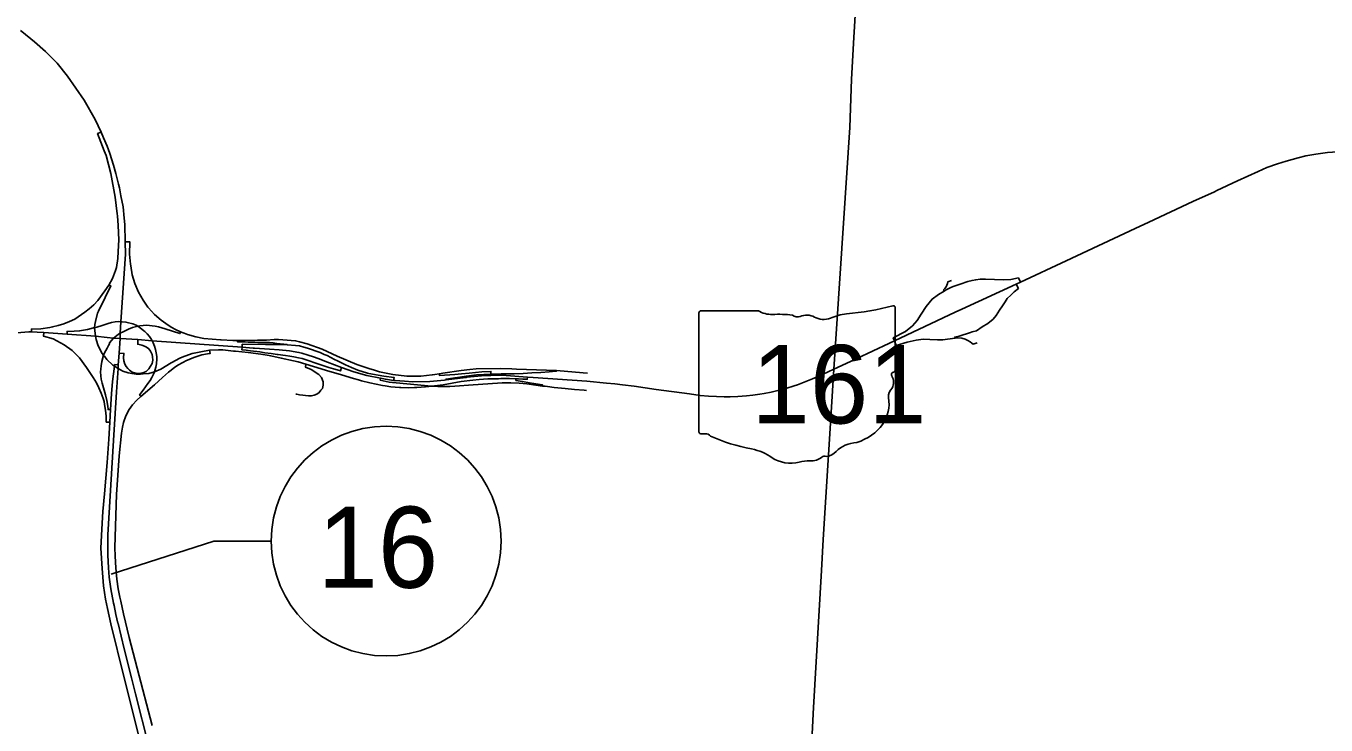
# Model space of a CAD drawing. Extents: x -1146 to -445, y -1283 to -822.
# Drawn here: x -822.8 to -765.1, y -965.9 to -934.9 of the extents above; entities that cross this region are included whole.
import ezdxf

# ---------------------------------------------------------------- set-up
doc = ezdxf.new("R2010")
doc.units = 0
for name, color, linetype in [('Default', 7, 'Continuous'), ('GM_X_Interchange_Ramps', 7, 'Continuous'), ('GM_X_Interstate_Route', 7, 'Continuous'), ('GM_X_State_Route', 7, 'Continuous'), ('GM_X_State_Shield', 7, 'Continuous'), ('GM_X_Township', 7, 'Continuous')]:
    doc.layers.add(name, color=color, linetype=linetype)

msp = doc.modelspace()

# ---------------------------------------------------------------- linework, layer by layer
at = {"layer": 'Default'}
msp.add_lwpolyline([(-811.901, -957.726), (-814.448, -957.726), (-818.997, -959.198)], dxfattribs=at)
msp.add_circle((-806.807, -957.726), 5.094, dxfattribs=at)
at = {"layer": 'GM_X_Interchange_Ramps'}
for points in [[(-819.448, -939.58), (-819.6, -939.647), (-819.307, -940.406), (-819.226, -940.617), (-819.015, -941.422), (-818.829, -942.461), (-818.73, -943.211), (-818.718, -943.301), (-818.686, -943.722), (-818.658, -944.358), (-818.683, -944.883), (-818.699, -945.182), (-818.768, -945.593), (-818.804, -945.721), (-818.948, -946.078), (-819.098, -946.367), (-819.275, -946.626), (-819.59, -947.048), (-819.772, -947.241), (-819.971, -947.421), (-820.168, -947.574), (-820.613, -947.874), (-820.85, -947.984), (-821.093, -948.082), (-821.344, -948.166), (-821.598, -948.227), (-821.723, -948.25), (-822.119, -948.304), (-822.534, -948.317), (-822.534, -948.445)], [(-797.886, -950.276), (-798.072, -950.259), (-799.257, -950.151), (-801.023, -950.096), (-801.236, -950.09), (-801.756, -950.069), (-802.815, -950.09), (-803.099, -950.118), (-803.474, -950.154), (-804.287, -950.272), (-804.454, -950.301), (-804.646, -950.334), (-804.765, -950.355), (-805.271, -950.409), (-805.889, -950.409), (-806.517, -950.332), (-807.104, -950.21), (-807.374, -950.132), (-807.534, -950.086), (-808.112, -949.893), (-808.976, -949.516), (-809.641, -949.212), (-810.31, -948.968), (-810.644, -948.885), (-810.824, -948.84), (-811.393, -948.791), (-811.583, -948.787), (-811.771, -948.788), (-812.109, -948.806), (-812.509, -948.815), (-813.053, -948.83), (-813.297, -948.829), (-813.407, -948.828), (-813.601, -948.826), (-814.123, -948.8), (-814.157, -948.798), (-814.523, -948.774), (-814.888, -948.736), (-815.252, -948.667), (-815.618, -948.558), (-815.77, -948.504), (-815.801, -948.493), (-815.926, -948.437), (-816.148, -948.337), (-816.316, -948.245), (-816.478, -948.147), (-816.789, -947.924), (-817.077, -947.669), (-817.347, -947.371), (-817.368, -947.343), (-817.586, -947.04), (-817.789, -946.68), (-817.95, -946.301), (-818.065, -945.91), (-818.131, -945.514), (-818.138, -945.446), (-818.186, -944.992), (-818.17, -944.456), (-818.379, -944.45)], [(-819.098, -946.367), (-819.016, -946.396), (-819.259, -946.914), (-819.56, -947.522), (-819.605, -947.612), (-819.7, -947.976), (-819.718, -948.11), (-819.738, -948.257), (-819.698, -948.64), (-819.67, -948.775), (-819.582, -949.062), (-819.477, -949.261), (-819.412, -949.383), (-819.341, -949.475), (-819.302, -949.525), (-819.188, -949.673), (-818.919, -949.92), (-818.847, -949.964), (-818.692, -950.074), (-818.488, -950.179), (-818.241, -950.265), (-818.078, -950.286), (-817.891, -950.315), (-817.705, -950.323), (-817.588, -950.312), (-817.331, -950.288), (-817.078, -950.215), (-816.805, -950.104), (-816.34, -949.824), (-816.307, -949.804), (-815.961, -949.616), (-815.781, -949.533), (-815.69, -949.5), (-815.406, -949.397), (-815.326, -949.381), (-815.022, -949.323), (-814.638, -949.25), (-814.247, -949.233), (-814.056, -949.242), (-813.578, -949.294), (-813.489, -949.304), (-812.92, -949.361), (-812.363, -949.436), (-811.999, -949.495), (-811.925, -949.51), (-811.461, -949.604), (-810.921, -949.726), (-810.707, -949.779), (-810.375, -949.874), (-809.684, -950.078), (-809.447, -950.15), (-808.794, -950.35), (-808.259, -950.512), (-808.038, -950.575), (-807.894, -950.615), (-807.528, -950.711), (-806.968, -950.826), (-806.846, -950.843), (-806.594, -950.877), (-806.217, -950.909), (-806.158, -950.912), (-805.835, -950.923), (-805.551, -950.917), (-805.453, -950.914), (-805.063, -950.887), (-804.77, -950.85), (-804.67, -950.837), (-804.278, -950.787), (-803.878, -950.716), (-803.475, -950.649), (-802.965, -950.587), (-802.689, -950.553), (-802.495, -950.54), (-802.302, -950.53), (-802.109, -950.523), (-801.832, -950.52), (-801.719, -950.519), (-801.526, -950.518), (-801.333, -950.519), (-801.051, -950.529), (-800.939, -950.527), (-800.745, -950.534), (-800.55, -950.542), (-800.542, -950.449)], [(-781.668, -946.432), (-781.764, -946.47), (-782.003, -946.598), (-782.063, -946.633), (-782.317, -946.782), (-782.596, -946.988), (-782.864, -947.319), (-783.082, -947.657), (-783.266, -947.941), (-783.472, -948.181), (-783.775, -948.428), (-784.322, -948.714), (-784.266, -948.841)], [(-781.743, -946.157), (-781.895, -946.218), (-781.913, -946.296), (-781.942, -946.378), (-781.98, -946.449), (-782.035, -946.524), (-782.09, -946.578), (-782.063, -946.633)], [(-778.681, -946.231), (-778.774, -946.051), (-779.104, -946.113), (-779.428, -946.132), (-780.238, -946.1), (-780.473, -946.106), (-780.661, -946.128), (-780.823, -946.161), (-781.015, -946.21), (-781.353, -946.324), (-781.539, -946.379), (-781.668, -946.432)], [(-780.822, -948.444), (-780.631, -948.394), (-780.377, -948.223), (-780.134, -948.076), (-779.897, -947.886), (-779.757, -947.713), (-779.607, -947.483), (-779.475, -947.292), (-779.361, -947.11), (-779.266, -946.967), (-779.113, -946.816), (-778.958, -946.665), (-778.774, -946.519), (-778.876, -946.323)], [(-817.69, -951.31), (-817.741, -951.246), (-817.679, -951.163), (-817.576, -951.023), (-817.473, -950.883), (-817.372, -950.74), (-817.277, -950.603), (-817.19, -950.464), (-817.118, -950.318), (-817.078, -950.215), (-817.026, -950.014), (-816.991, -949.857), (-816.987, -949.805), (-816.979, -949.695), (-816.982, -949.535), (-817.002, -949.376), (-817.036, -949.221), (-817.083, -949.071), (-817.143, -948.923), (-817.188, -948.838), (-817.216, -948.786), (-817.301, -948.655), (-817.402, -948.532), (-817.512, -948.422), (-817.548, -948.392), (-817.634, -948.32), (-817.824, -948.195), (-817.899, -948.153), (-818.043, -948.09), (-818.295, -948.024), (-818.349, -948.01), (-818.507, -947.992), (-818.567, -947.992), (-818.668, -947.99), (-818.825, -948.002), (-818.984, -948.027), (-819.138, -948.065), (-819.439, -948.169), (-819.738, -948.257), (-819.789, -948.271), (-820.045, -948.338), (-820.401, -948.398), (-820.644, -948.415), (-820.952, -948.425), (-820.958, -948.549)], [(-815.926, -948.437), (-815.95, -948.517), (-816.279, -948.418), (-816.601, -948.315), (-816.902, -948.224), (-817.055, -948.187), (-817.43, -948.142), (-817.725, -948.172), (-817.824, -948.195), (-818.052, -948.256), (-818.232, -948.328), (-818.433, -948.424), (-818.594, -948.497), (-818.638, -948.517), (-818.753, -948.602), (-818.901, -948.721), (-819.067, -948.936), (-819.081, -948.967), (-819.121, -949.05), (-819.175, -949.173), (-819.292, -949.376), (-819.325, -949.448), (-819.341, -949.475), (-819.414, -949.755), (-819.445, -949.943), (-819.461, -950.093), (-819.469, -950.221), (-819.458, -950.394), (-819.45, -950.541), (-819.398, -950.723), (-819.251, -951.231), (-819.187, -951.491), (-819.145, -951.739), (-819.14, -951.887), (-819.024, -951.888)], [(-821.988, -948.471), (-821.995, -948.64), (-821.572, -948.759), (-821.088, -949.019), (-820.732, -949.263), (-820.407, -949.602), (-820.092, -950.029), (-819.794, -950.463), (-819.656, -950.707), (-819.541, -950.926), (-819.442, -951.166), (-819.36, -951.4), (-819.316, -951.535), (-819.296, -951.667), (-819.252, -951.912), (-819.233, -952.056), (-819.228, -952.183), (-819.219, -952.444), (-819.064, -952.443)], [(-817.811, -948.787), (-817.824, -948.994), (-817.643, -949.028), (-817.527, -949.07), (-817.429, -949.123), (-817.334, -949.2), (-817.254, -949.303), (-817.186, -949.446), (-817.162, -949.557), (-817.159, -949.695), (-817.188, -949.84), (-817.252, -949.967), (-817.331, -950.089), (-817.455, -950.195), (-817.596, -950.256), (-817.683, -950.279), (-817.818, -950.285), (-817.958, -950.261), (-818.067, -950.224), (-818.189, -950.147), (-818.268, -950.073), (-818.339, -949.986), (-818.4, -949.869), (-818.443, -949.732), (-818.451, -949.599), (-818.435, -949.396), (-818.65, -949.39)], [(-784.266, -948.841), (-784.186, -949.044), (-783.706, -948.899), (-783.3, -948.809), (-782.996, -948.76), (-782.699, -948.788), (-782.353, -948.792), (-782.128, -948.795), (-781.91, -948.767), (-781.573, -948.726), (-781.436, -948.706), (-781.286, -948.721), (-781.134, -948.771), (-781.009, -948.823), (-780.907, -948.88), (-780.833, -948.941), (-780.781, -948.993), (-780.596, -948.923)], [(-781.573, -948.726), (-781.591, -948.672), (-781.405, -948.632), (-780.901, -948.47), (-780.822, -948.444)], [(-817.188, -965.901), (-817.841, -963.357), (-818.196, -961.995), (-818.449, -960.944), (-818.573, -960.385), (-818.609, -960.208), (-818.686, -959.835), (-818.746, -959.407), (-818.799, -958.911), (-818.824, -958.395), (-818.844, -958.003), (-818.759, -955.652), (-818.643, -953.947), (-818.547, -952.935), (-818.504, -952.673), (-818.452, -952.458), (-818.357, -952.167), (-818.206, -951.89), (-818.048, -951.678), (-817.863, -951.469), (-817.69, -951.31), (-817.086, -950.788), (-816.729, -950.469), (-816.462, -950.231), (-816.345, -950.14), (-816.173, -950.007), (-816.016, -949.902), (-815.852, -949.811), (-815.798, -949.783), (-815.682, -949.725), (-815.51, -949.647), (-815.334, -949.576), (-814.974, -949.468), (-814.731, -949.423), (-814.606, -949.399), (-814.638, -949.25)], [(-811.202, -949.025), (-811.2, -948.997), (-811.65, -948.952), (-811.817, -948.936), (-811.98, -948.922), (-812.105, -948.912), (-812.492, -948.909), (-812.634, -948.907), (-812.777, -948.904), (-812.921, -948.899), (-813.405, -948.881), (-813.407, -948.828)], [(-813.197, -949.124), (-813.205, -949.237), (-813.009, -949.256), (-812.826, -949.278), (-812.412, -949.334), (-812.192, -949.367), (-811.907, -949.407), (-811.638, -949.441), (-811.59, -949.447), (-811.395, -949.475), (-811.269, -949.494), (-811.085, -949.518), (-810.898, -949.553), (-810.695, -949.598)], [(-810.656, -949.063), (-810.831, -949.05), (-811.202, -949.025), (-811.494, -949.006), (-811.795, -948.998), (-812.16, -949.004), (-813.188, -948.99), (-813.197, -949.124)], [(-806.475, -950.596), (-806.456, -950.466), (-806.915, -950.408), (-807.575, -950.284), (-807.631, -950.274), (-808.061, -950.135), (-808.338, -950.027), (-808.607, -949.906), (-808.962, -949.733), (-809.091, -949.673), (-809.428, -949.494), (-809.549, -949.44), (-809.734, -949.358), (-810.288, -949.166), (-810.459, -949.115), (-810.656, -949.063)], [(-818.683, -949.902), (-818.837, -949.885), (-818.847, -949.964), (-818.94, -950.64), (-818.98, -951.188), (-819.024, -951.888), (-819.064, -952.443), (-819.11, -953.208), (-819.174, -954.237), (-819.294, -955.633), (-819.368, -956.418), (-819.418, -957.196), (-819.461, -958.041), (-819.4, -958.938), (-819.335, -959.712), (-819.246, -960.303), (-819.16, -960.718), (-819.021, -961.389), (-818.434, -963.734), (-817.723, -966.557)], [(-810.375, -949.874), (-810.39, -950.005), (-810.125, -950.115), (-809.796, -950.328), (-809.677, -950.465), (-809.601, -950.66), (-809.601, -950.808), (-809.633, -950.951), (-809.697, -951.03), (-809.773, -951.14), (-809.884, -951.207), (-810.003, -951.257), (-810.122, -951.277), (-810.251, -951.274), (-810.385, -951.265), (-810.504, -951.257), (-810.65, -951.236), (-810.763, -951.213), (-810.807, -951.206)], [(-810.695, -949.598), (-810.528, -949.624), (-809.655, -949.923), (-809.348, -950.02), (-809.141, -950.085), (-808.975, -950.133), (-808.828, -950.176), (-808.789, -950.027)], [(-807.051, -950.504), (-807.067, -950.585), (-806.677, -950.669), (-806.522, -950.688), (-806.358, -950.707), (-805.419, -950.798), (-804.953, -950.839), (-804.77, -950.85), (-804.51, -950.865), (-804.295, -950.871), (-803.984, -950.864), (-803.758, -950.848), (-802.954, -950.79), (-802.302, -950.743), (-801.659, -950.707), (-801.277, -950.703), (-800.909, -950.724), (-800.572, -950.754), (-800.163, -950.811), (-799.871, -950.845), (-799.762, -950.857), (-799.647, -950.871), (-799.361, -950.904), (-798.874, -950.96), (-798.458, -950.996), (-798.022, -951.035), (-797.927, -951.043)], [(-802.17, -950.375), (-802.171, -950.32), (-802.161, -950.194), (-802.56, -950.22), (-803.133, -950.27), (-803.471, -950.304), (-803.767, -950.335), (-804.447, -950.374), (-804.454, -950.301)], [(-799.257, -950.151), (-799.261, -950.192), (-799.585, -950.22), (-799.955, -950.241), (-800.342, -950.262), (-800.733, -950.285), (-801.137, -950.301), (-801.711, -950.308), (-802.171, -950.32), (-802.479, -950.332), (-802.796, -950.353), (-803.255, -950.407), (-803.535, -950.45), (-803.766, -950.487), (-804.149, -950.54), (-804.15, -950.577)], [(-801.051, -950.529), (-801.053, -950.596), (-800.767, -950.646), (-800.444, -950.701), (-799.868, -950.796), (-799.871, -950.845)]]:
    msp.add_lwpolyline(points, dxfattribs=at)
at = {"layer": 'GM_X_Interstate_Route'}
for points in [[(-823.019, -935.068), (-822.957, -935.112), (-822.398, -935.578), (-821.906, -936.013), (-821.402, -936.526), (-820.942, -937.106), (-820.2, -938.171), (-819.704, -939.027), (-819.448, -939.58), (-819.333, -939.832), (-819.178, -940.203), (-819.059, -940.53), (-818.891, -941.046), (-818.788, -941.415), (-818.67, -941.884), (-818.633, -942.053), (-818.569, -942.406), (-818.474, -942.902), (-818.421, -943.397), (-818.396, -943.686), (-818.379, -944.45)], [(-818.379, -944.45), (-818.372, -944.999), (-818.567, -947.992), (-818.594, -948.497), (-818.595, -948.526)], [(-818.598, -948.649), (-818.6, -948.736), (-818.65, -949.39)], [(-818.595, -948.526), (-818.598, -948.649)], [(-818.65, -949.39), (-818.683, -949.902)], [(-818.683, -949.902), (-818.692, -950.074), (-818.759, -951.101), (-818.822, -952.061), (-818.901, -953.259), (-819.145, -957.445), (-819.153, -958.331), (-819.151, -958.354)], [(-819.151, -958.354), (-819.114, -958.909), (-819.082, -959.318), (-819.008, -959.841), (-818.895, -960.477), (-818.873, -960.583)], [(-818.873, -960.583), (-818.791, -960.974), (-818.701, -961.358)], [(-818.701, -961.358), (-818.697, -961.375), (-818.421, -962.499), (-818.092, -963.796)], [(-818.092, -963.796), (-817.914, -964.494), (-816.765, -969.055), (-816.7, -969.313), (-816.158, -971.559)]]:
    msp.add_lwpolyline(points, dxfattribs=at)
at = {"layer": 'GM_X_State_Route'}
for points in [[(-769.971, -942.178), (-769.057, -941.746), (-768.141, -941.323), (-767.751, -941.156), (-767.285, -940.986), (-766.901, -940.865), (-766.374, -940.723), (-766.031, -940.64), (-765.578, -940.557), (-765.064, -940.489), (-764.619, -940.45), (-764.103, -940.437), (-763.354, -940.47), (-762.063, -940.554), (-761.846, -940.568), (-759.773, -940.701), (-757.589, -940.83), (-757.27, -940.85), (-754.647, -941.023)], [(-781.576, -947.572), (-781.281, -947.433), (-778.876, -946.323), (-778.681, -946.231), (-776.652, -945.285), (-773.597, -943.852), (-772.992, -943.578), (-771.04, -942.667), (-770.077, -942.228), (-769.971, -942.178)], [(-784.266, -948.841), (-781.576, -947.572)], [(-823.31, -948.5), (-823.309, -948.5), (-823.009, -948.467), (-822.831, -948.452), (-822.65, -948.447), (-822.534, -948.445), (-822.279, -948.461), (-821.988, -948.471), (-820.958, -948.549), (-819.698, -948.64), (-819.18, -948.693)], [(-819.18, -948.693), (-818.901, -948.721), (-818.6, -948.736), (-817.811, -948.787), (-817.188, -948.838), (-813.197, -949.124), (-812.711, -949.159), (-812.647, -949.164), (-811.978, -949.212), (-811.549, -949.243), (-811.096, -949.284), (-810.677, -949.356), (-810.545, -949.392)], [(-810.545, -949.392), (-810.259, -949.472), (-810.035, -949.548), (-809.825, -949.62), (-809.41, -949.788), (-808.789, -950.027), (-808.243, -950.212), (-807.66, -950.383), (-807.051, -950.504)], [(-790.244, -951.206), (-790.047, -951.176), (-789.736, -951.116), (-789.501, -951.062), (-789.078, -950.949), (-788.719, -950.839), (-788.561, -950.787), (-788.341, -950.709), (-788.119, -950.622), (-787.897, -950.529), (-787.464, -950.332), (-786.955, -950.098), (-786.222, -949.751), (-785.458, -949.399), (-784.266, -948.841)], [(-807.051, -950.504), (-806.836, -950.543), (-806.475, -950.596), (-806.412, -950.605), (-805.993, -950.624), (-805.63, -950.653), (-804.877, -950.639), (-804.22, -950.586), (-804.15, -950.577), (-803.777, -950.529), (-803.261, -950.46), (-803.228, -950.456)], [(-803.228, -950.456), (-802.897, -950.416), (-802.573, -950.392), (-802.243, -950.376), (-802.17, -950.375), (-801.835, -950.371), (-801.479, -950.378), (-800.542, -950.449)], [(-800.542, -950.449), (-800.284, -950.47), (-797.906, -950.626), (-797.031, -950.718), (-796.672, -950.752), (-796.334, -950.792), (-795.817, -950.856), (-794.827, -950.994), (-793.362, -951.198), (-792.881, -951.26), (-792.519, -951.295), (-792.161, -951.316), (-791.82, -951.324), (-791.582, -951.322)], [(-791.582, -951.322), (-791.558, -951.322), (-791.208, -951.31), (-790.83, -951.28), (-790.544, -951.251), (-790.244, -951.206)]]:
    msp.add_lwpolyline(points, dxfattribs=at)
at = {"layer": 'GM_X_State_Shield'}
for p, q in [((-792.935, -947.596), (-792.935, -952.879)), ((-790.302, -947.505), (-792.85, -947.505)), ((-784.234, -950.137), (-784.234, -947.374)), ((-784.235, -950.137), (-784.234, -950.137))]:
    msp.add_line(p, q, dxfattribs=at)
for centre, major_axis, start_param, end_param in [((-792.836, -947.584), (0.101, 0), 1.712693, 3.28349), ((-789.695, -946.891), (0.978, 0), 4.042523, 4.731795), ((-789.371, -950.471), (3.51, 0), 1.404758, 1.657858), ((-786.157, -949.118), (1.856, 0), 1.699011, 2.107814), ((-787.334, -940.302), (9.227, 0), 4.814394, 5.042369), ((-784.331, -947.362), (0.0969, 0), 6.141152, 7.989035), ((-788.574, -947.557), (0.282, 0), 3.836095, 5.185415), ((-788.16, -948.168), (0.586, 0), 0.950623, 2.079405), ((-787.403, -947.33), (0.705, 0), 4.081561, 5.145723), ((-784.257, -950.34), (0.15, 0), 1.883978, 3.671073), ((-785.21, -950.69), (0.9, 0), 5.934695, 6.695948), ((-784.338, -950.148), (0.104, 0), 5.05454, 6.418171), ((-783.887, -951.294), (0.655, 0), 2.387724, 3.262537), ((-786.817, -951.646), (2.308, 0), 5.101752, 6.440018), ((-792.835, -952.89), (0.102, 0), 3.00124, 4.508301), ((-792.819, -952.35), (0.776, 0), 4.665946, 4.897461), ((-792.661, -953.184), (0.28, 0), 0.519207, 1.627899), ((-789.128, -948.437), (6.663, 0), 4.195997, 4.488961), ((-785.844, -954.362), (1.264, 0), 1.647645, 2.488434), ((-791.114, -955.252), (2.085, 0), 0.823519, 1.323587), ((-787.998, -953.605), (0.705, 0), 4.691044, 5.507374), ((-787.361, -954.117), (0.198, 0), 1.147584, 2.315152), ((-787.445, -953.391), (0.746, 0), 4.937069, 5.64225), ((-788.859, -953.21), (1.323, 0), 4.026481, 4.996735), ((-788.095, -955.036), (1.087, 0), 1.495662, 1.94098)]:
    msp.add_ellipse(centre, major_axis=major_axis, ratio=0.8, start_param=start_param, end_param=end_param, dxfattribs=at)
at = {"layer": 'GM_X_Township'}
msp.add_lwpolyline([(-785.887, -932.425), (-786.067, -935.383), (-786.179, -937.232), (-786.252, -939.38), (-786.955, -950.098), (-787.081, -952.015), (-787.425, -957.66), (-787.508, -959.023), (-787.857, -965.105), (-787.983, -967.439)], dxfattribs=at)

# ---------------------------------------------------------------- texts
at = {"layer": 'Default'}
msp.add_text('16', height=3.6, dxfattribs=at).set_placement((-809.85, -959.795))
at = {"layer": 'GM_X_State_Shield'}
msp.add_text('161', height=3.4805, dxfattribs=at).set_placement((-790.609, -952.506))

doc.saveas('drawing.dxf')
